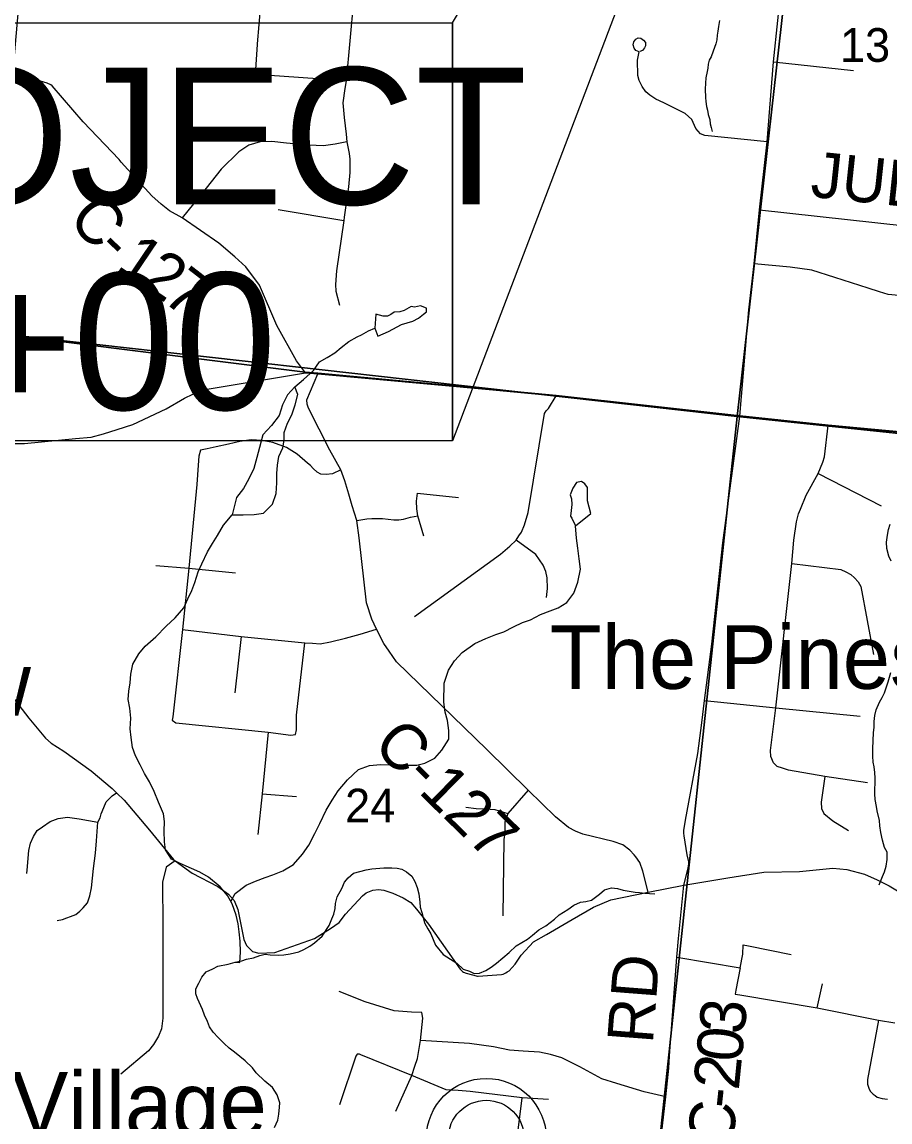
# Model space of a CAD drawing. Extents: x 0 to 43.4, y -8.1 to 22.
# Drawn here: x 5.839 to 6.917, y 16.475 to 17.842 of the extents above; entities that cross this region are included whole.
import ezdxf

# ---------------------------------------------------------------- set-up
doc = ezdxf.new("R2010")
doc.units = 0
for name, color, linetype in [('GM_X_Corporation', 7, 'Continuous'), ('GM_X_County_Road', 7, 'Continuous'), ('GM_X_County_Road_Text', 7, 'Continuous'), ('GM_X_Minor_Lake', 7, 'Continuous'), ('GM_X_Minor_River', 7, 'Continuous'), ('GM_X_Section_Text', 7, 'Continuous'), ('GM_X_Township_Road', 7, 'Continuous'), ('GM_X_Unincorporated', 7, 'Continuous'), ('GM_X_Unincorporated_Text', 7, 'Continuous'), ('SH_Masking', 7, 'Continuous'), ('SH_Text', 7, 'Continuous')]:
    doc.layers.add(name, color=color, linetype=linetype)

msp = doc.modelspace()

# ---------------------------------------------------------------- linework, layer by layer
at = {"layer": 'GM_X_Corporation'}
for points in [[(6.8431, 18.3799), (6.7271, 17.3517), (5.7989, 17.456), (5.8893, 18.4791)], [(6.8431, 18.3799), (7.8526, 18.2674), (7.7575, 17.2431), (6.7271, 17.3517)], [(6.7271, 17.3517), (6.6267, 16.4119), (5.7092, 16.4607), (5.7989, 17.456)], [(7.7575, 17.2431), (7.6501, 16.228), (6.6267, 16.4119), (6.7271, 17.3517)]]:
    msp.add_lwpolyline(points, close=True, dxfattribs=at)
for points in [[(6.9337, 17.3322), (6.8401, 17.341), (6.7303, 17.3528), (6.5022, 17.378), (6.4189, 17.3857), (6.2062, 17.4054), (6.1906, 17.4067), (5.7944, 17.4564), (5.4373, 17.5131), (4.8521, 17.6061), (4.4612, 17.6488), (4.3821, 17.6581), (4.1644, 17.6753)], [(4.1644, 17.6753), (4.3821, 17.6581), (4.4612, 17.6488), (4.8521, 17.6061), (5.4373, 17.5131), (5.7944, 17.4564), (6.1906, 17.4067), (6.2062, 17.4054), (6.4189, 17.3857), (6.5022, 17.378), (6.7303, 17.3528), (6.8401, 17.341), (6.9337, 17.3322)]]:
    msp.add_lwpolyline(points, dxfattribs=at)
at = {"layer": 'GM_X_County_Road'}
msp.add_line((6.1909, 17.4062), (6.2065, 17.4049), dxfattribs=at)
for points in [[(6.755, 17.6085), (6.7645, 17.6929), (6.7721, 17.7923), (6.7884, 17.9468), (6.7919, 17.9787), (6.8164, 18.1721), (6.8285, 18.2944), (6.8309, 18.3175)], [(5.9623, 17.6678), (5.9596, 17.6709), (5.915, 17.7177), (5.8763, 17.7626), (5.8748, 17.7638), (5.8703, 17.7658), (5.8485, 17.7726), (5.8243, 17.7859)], [(6.1909, 17.4062), (6.1798, 17.4209), (6.1554, 17.4646), (6.1338, 17.5151), (6.117, 17.5377), (6.1032, 17.55), (6.0836, 17.5671), (6.0379, 17.5987), (6.0222, 17.6072), (6.012, 17.6154), (6.0002, 17.626), (5.9623, 17.6678)], [(6.7305, 17.3523), (6.7417, 17.4843), (6.7481, 17.5416), (6.755, 17.6085)], [(6.755, 17.6085), (6.9735, 17.5845), (7.2654, 17.5541)], [(5.8217, 17.3184), (5.8422, 17.3182), (5.9056, 17.3244), (5.9247, 17.3259), (5.9403, 17.3303), (5.9573, 17.3355), (5.9766, 17.342), (6.018, 17.3613), (6.041, 17.3746), (6.0616, 17.3843), (6.1909, 17.4062)], [(6.6168, 16.7608), (6.61, 16.7869), (6.6061, 16.7976), (6.6012, 16.8049), (6.5991, 16.8073), (6.5939, 16.813), (6.585, 16.8199), (6.5733, 16.8237), (6.5355, 16.8329), (6.5262, 16.8367), (6.5175, 16.8412), (6.5015, 16.8545), (6.4676, 16.8877), (6.4161, 16.9382), (6.304, 17.0472), (6.2948, 17.0603), (6.2885, 17.07), (6.2791, 17.0875), (6.2733, 17.0999), (6.2669, 17.1205), (6.2578, 17.2011), (6.2547, 17.2226), (6.2489, 17.2407), (6.2448, 17.2553), (6.24, 17.272), (6.2351, 17.2857), (6.2214, 17.31), (6.1948, 17.3621), (6.193, 17.3671), (6.1928, 17.3724), (6.2065, 17.4049)], [(6.2065, 17.4049), (6.4191, 17.3852), (6.5024, 17.3775), (6.7305, 17.3523), (6.8403, 17.3405), (6.934, 17.3317), (7.0194, 17.3221), (7.1459, 17.3085), (7.2379, 17.2981), (7.3491, 17.2862), (7.3995, 17.281), (7.6127, 17.2515), (7.6512, 17.2473), (7.707, 17.2463), (7.7489, 17.2401), (7.8001, 17.2378), (7.885, 17.2341), (7.9438, 17.2315), (8.0044, 17.2296), (8.0566, 17.228), (8.1392, 17.2232), (8.1943, 17.2214)], [(6.6432, 16.5578), (6.652, 16.6803), (6.6544, 16.7036), (6.6608, 16.7698), (6.6662, 16.7909), (6.6671, 16.7961), (6.667, 16.7987), (6.6651, 16.8073), (6.6613, 16.8309), (6.6609, 16.8341), (6.6608, 16.8374), (6.663, 16.8502), (6.6784, 16.9333), (6.6831, 16.9711), (6.6866, 16.9991), (6.6955, 17.0691), (6.7092, 17.1947), (6.7305, 17.3523)], [(5.8185, 17.0146), (5.8473, 16.9772), (5.868, 16.9524), (5.8751, 16.9462), (5.8908, 16.936), (5.9251, 16.9118), (5.9508, 16.8896), (5.9565, 16.8842), (5.966, 16.8752), (5.9975, 16.8381), (6.027, 16.8014), (6.0292, 16.7998), (6.0382, 16.7932), (6.0505, 16.7846), (6.0824, 16.768), (6.0955, 16.7586), (6.1025, 16.7505), (6.1072, 16.7394), (6.1099, 16.7249), (6.1143, 16.7021), (6.1176, 16.6948), (6.1254, 16.6874), (6.1333, 16.685), (6.153, 16.6861), (6.2023, 16.7036), (6.2223, 16.716), (6.2327, 16.7234), (6.2406, 16.7338), (6.2619, 16.7565), (6.2665, 16.7602), (6.2746, 16.7634), (6.2816, 16.7641), (6.2882, 16.7635), (6.2995, 16.7599), (6.3123, 16.7539), (6.3217, 16.748), (6.3291, 16.7399), (6.3438, 16.7214), (6.3832, 16.6655), (6.386, 16.6624), (6.3873, 16.6615), (6.3906, 16.6604), (6.4045, 16.6568), (6.4054, 16.6567), (6.4346, 16.6587), (6.4366, 16.6592), (6.4397, 16.6608), (6.4415, 16.6618), (6.4441, 16.6634), (6.4516, 16.6716), (6.459, 16.6828), (6.4742, 16.6992), (6.4903, 16.7083), (6.5222, 16.727), (6.5487, 16.7423), (6.5594, 16.7468)], [(6.6168, 16.7608), (6.6608, 16.7698), (6.7156, 16.7789), (6.7602, 16.7859), (6.8046, 16.7868), (6.846, 16.7908), (6.8634, 16.7893), (6.8853, 16.7835), (6.901, 16.7764), (6.916, 16.7688), (6.9303, 16.7602)], [(6.5594, 16.7468), (6.5701, 16.7513), (6.6168, 16.7608)], [(6.6315, 16.4453), (6.6384, 16.5068), (6.6421, 16.5425), (6.6432, 16.5578)]]:
    msp.add_lwpolyline(points, dxfattribs=at)
at = {"layer": 'GM_X_Minor_Lake'}
for points in [[(6.2772, 17.4615), (6.2811, 17.4515), (6.2942, 17.4573), (6.3103, 17.4659), (6.3245, 17.4701), (6.3314, 17.4741), (6.3376, 17.4789), (6.3415, 17.4818), (6.3412, 17.4864), (6.3337, 17.4892), (6.3265, 17.4875), (6.3223, 17.4884), (6.3135, 17.4833), (6.3081, 17.4816), (6.3013, 17.4814), (6.297, 17.4784), (6.2928, 17.4763), (6.2875, 17.4764), (6.2784, 17.4789)], [(6.2784, 17.4789), (6.2772, 17.4615)], [(6.1, 17.2297), (6.1135, 17.2297), (6.1272, 17.2301), (6.139, 17.2317), (6.1499, 17.2428), (6.1548, 17.2563), (6.1555, 17.2692), (6.1555, 17.281), (6.1561, 17.2912), (6.1579, 17.3022), (6.1628, 17.3127), (6.1645, 17.3225), (6.1644, 17.332), (6.1689, 17.3436), (6.1741, 17.3537), (6.1782, 17.3662), (6.1816, 17.379), (6.1777, 17.3886), (6.1687, 17.3786), (6.1627, 17.3662), (6.1585, 17.353), (6.1487, 17.3408), (6.1381, 17.3289), (6.1339, 17.3134), (6.1306, 17.301), (6.1268, 17.287), (6.1207, 17.2743), (6.114, 17.2623), (6.1053, 17.2512)], [(6.5262, 17.216), (6.5455, 17.2311), (6.5414, 17.2472), (6.5414, 17.2635), (6.5378, 17.2681), (6.5337, 17.2709), (6.5276, 17.2699), (6.5232, 17.2628), (6.5199, 17.2546), (6.5213, 17.2496), (6.5219, 17.2424), (6.521, 17.2352), (6.52, 17.228), (6.5218, 17.2253)], [(6.1053, 17.2512), (6.1, 17.2297)], [(6.5218, 17.2253), (6.5262, 17.216)]]:
    msp.add_lwpolyline(points, dxfattribs=at)
at = {"layer": 'GM_X_Minor_River'}
for points in [[(6.7053, 17.8436), (6.7039, 17.836), (6.7033, 17.8303), (6.7023, 17.8254), (6.7018, 17.8197), (6.7008, 17.8148), (6.6975, 17.8054), (6.695, 17.7987), (6.6925, 17.7942), (6.6912, 17.7893), (6.6907, 17.7844), (6.6898, 17.7803), (6.6884, 17.7723), (6.6878, 17.7659), (6.6875, 17.7583), (6.6879, 17.748), (6.6881, 17.7431), (6.689, 17.7369), (6.6904, 17.7323), (6.691, 17.727), (6.693, 17.7205), (6.6936, 17.7151), (6.695, 17.7109), (6.6959, 17.7059)], [(6.1777, 17.3886), (6.1886, 17.3978), (6.201, 17.4089), (6.2085, 17.4197), (6.2178, 17.4251), (6.2274, 17.4309), (6.2352, 17.4376), (6.2449, 17.4449), (6.2553, 17.4507), (6.2606, 17.4532), (6.2691, 17.4583), (6.2772, 17.4615)], [(6.1043, 16.6739), (6.1094, 16.6735), (6.1105, 16.6863), (6.11, 16.7), (6.1088, 16.7118), (6.1076, 16.7217), (6.1048, 16.7324), (6.1002, 16.7466), (6.094, 16.757), (6.0852, 16.7675), (6.0707, 16.7796), (6.0599, 16.7856), (6.0493, 16.7904), (6.0355, 16.7965), (6.0246, 16.8021), (6.0173, 16.8136), (6.016, 16.8235), (6.0156, 16.8368), (6.0159, 16.8486), (6.0146, 16.8581), (6.0085, 16.8727), (6.0032, 16.8858), (5.9974, 16.8981), (5.9912, 16.9085), (5.9858, 16.9192), (5.98, 16.9304), (5.9761, 16.9408), (5.9745, 16.9529), (5.9733, 16.964), (5.974, 16.9769), (5.9728, 16.9894), (5.9708, 17.0001), (5.9718, 17.0107), (5.9732, 17.021), (5.9743, 17.0316), (5.9768, 17.044), (5.984, 17.0568), (5.9918, 17.0664), (6.0054, 17.0779), (6.0179, 17.0912), (6.0292, 17.1016), (6.0401, 17.1142), (6.0449, 17.1251), (6.0501, 17.1356), (6.0538, 17.1454), (6.0576, 17.159), (6.0624, 17.1687), (6.0692, 17.1838), (6.0755, 17.1942), (6.0819, 17.204), (6.0894, 17.2167), (6.1, 17.2297)], [(6.0985, 16.7495), (6.1036, 16.7594), (6.1175, 16.7697), (6.129, 16.7748), (6.1409, 16.779), (6.1505, 16.7826), (6.1628, 16.7876), (6.1762, 16.7952), (6.1872, 16.8082), (6.1951, 16.8194), (6.2026, 16.8337), (6.2087, 16.8464), (6.2167, 16.8626), (6.2242, 16.8753), (6.2317, 16.8869), (6.2431, 16.9006), (6.257, 16.9132), (6.2704, 16.9182), (6.2841, 16.9194), (6.297, 16.919), (6.3084, 16.9195), (6.3183, 16.9189), (6.3293, 16.9186), (6.3392, 16.921), (6.3515, 16.9272), (6.3605, 16.9372), (6.3692, 16.951), (6.3691, 16.9617), (6.3675, 16.9742), (6.3647, 16.9846), (6.3628, 16.9968), (6.3634, 17.0207), (6.3687, 17.0369), (6.3762, 17.0481), (6.3856, 17.0585), (6.4014, 17.0699), (6.4149, 17.076), (6.4275, 17.081), (6.4375, 17.0845), (6.4494, 17.0907), (6.4606, 17.0957), (6.4705, 17.0993), (6.4828, 17.1058), (6.4951, 17.1104), (6.5047, 17.114), (6.5155, 17.1209), (6.5245, 17.1325), (6.5294, 17.146), (6.5325, 17.1623), (6.5309, 17.1749), (6.5293, 17.1882), (6.5277, 17.2008), (6.5262, 17.216)], [(6.9183, 17.172), (6.9153, 17.1782), (6.9128, 17.1877), (6.9126, 17.1957), (6.9139, 17.2044), (6.9152, 17.2116), (6.9172, 17.218)], [(6.9033, 16.7701), (6.9077, 16.7803), (6.9101, 16.7863), (6.9121, 16.7931), (6.9134, 16.8015), (6.9132, 16.8106), (6.9099, 16.8164), (6.9077, 16.8255), (6.9056, 16.8351), (6.9043, 16.8435), (6.904, 16.8499), (6.9011, 16.8618), (6.9001, 16.8675), (6.8987, 16.8759), (6.8981, 16.8831), (6.8982, 16.8892), (6.8987, 16.896), (6.8985, 16.9025), (6.8982, 16.9097), (6.8972, 16.9166), (6.8961, 16.9223), (6.8955, 16.9299), (6.8957, 16.939), (6.8964, 16.9592), (6.8973, 16.9656), (6.8974, 16.9728), (6.898, 16.9804), (6.8996, 16.9876), (6.904, 16.997), (6.9072, 17.0027), (6.9099, 17.0087), (6.9123, 17.0148), (6.9148, 17.0223), (6.918, 17.034)], [(6.1524, 16.4688), (6.1567, 16.4778), (6.158, 16.4854), (6.1589, 16.4938), (6.1594, 16.4994), (6.1558, 16.5094), (6.1502, 16.5182), (6.1404, 16.5264), (6.1296, 16.5365), (6.1251, 16.5426), (6.1161, 16.5515), (6.1029, 16.5624), (6.0961, 16.5671), (6.0901, 16.5729), (6.0826, 16.5803), (6.0763, 16.5872), (6.0718, 16.5938), (6.0692, 16.6003), (6.0656, 16.6083), (6.063, 16.6152), (6.0568, 16.629), (6.055, 16.6347), (6.0547, 16.6408), (6.0587, 16.648), (6.0622, 16.6555), (6.0677, 16.6619), (6.0758, 16.6659), (6.0823, 16.6692), (6.095, 16.6717), (6.1038, 16.6738), (6.1119, 16.6755), (6.118, 16.6777), (6.1264, 16.6795), (6.1345, 16.6824), (6.141, 16.6838), (6.1471, 16.6833), (6.1574, 16.6827), (6.1643, 16.6833), (6.172, 16.6843), (6.1827, 16.6868), (6.1889, 16.6897), (6.1966, 16.6938), (6.2024, 16.6982), (6.2117, 16.7061), (6.2203, 16.7196), (6.2239, 16.7279), (6.2263, 16.7336), (6.228, 16.7407), (6.2285, 16.7468), (6.2305, 16.7551), (6.2361, 16.7653), (6.2397, 16.7732), (6.244, 16.7789), (6.2506, 16.7844), (6.2663, 16.7887), (6.2736, 16.7901), (6.2885, 16.791), (6.2984, 16.7912), (6.3049, 16.7907), (6.3106, 16.7894), (6.3166, 16.7863), (6.323, 16.7809), (6.3267, 16.774), (6.3297, 16.7667), (6.3318, 16.7587), (6.3331, 16.7484)], [(6.3331, 16.7484), (6.3334, 16.7423), (6.3356, 16.7358), (6.3388, 16.7228), (6.3429, 16.7155), (6.3466, 16.709), (6.3524, 16.6952), (6.3621, 16.6836), (6.3712, 16.6777), (6.3791, 16.6727), (6.387, 16.6653), (6.3946, 16.6629), (6.4007, 16.6601), (6.4071, 16.6604), (6.4152, 16.6637), (6.4218, 16.6677), (6.4284, 16.6729), (6.4439, 16.6859), (6.4528, 16.6942), (6.4598, 16.6986), (6.4667, 16.7026), (6.4729, 16.7075), (6.4807, 16.7142), (6.4896, 16.7193), (6.5004, 16.7275), (6.5062, 16.7327), (6.5167, 16.7394), (6.5244, 16.7449), (6.5325, 16.7486), (6.539, 16.7493), (6.5463, 16.751), (6.556, 16.7585), (6.5622, 16.764), (6.571, 16.7662), (6.5786, 16.7653), (6.5855, 16.7636), (6.5931, 16.7624), (6.6003, 16.7611), (6.606, 16.7606), (6.6125, 16.7597), (6.6182, 16.7592), (6.6247, 16.7587)]]:
    msp.add_lwpolyline(points, dxfattribs=at)
at = {"layer": 'GM_X_Township_Road'}
for p, q in [((6.7721, 17.7923), (6.8717, 17.7815)), ((6.157, 17.6088), (6.2385, 17.5951)), ((6.8276, 17.2811), (6.9059, 17.241)), ((6.111, 17.0784), (6.1032, 17.0084)), ((6.1371, 16.8831), (6.1798, 16.8796)), ((6.8266, 16.6171), (6.833, 16.647))]:
    msp.add_line(p, q, dxfattribs=at)
for points in [[(6.1315, 17.8148), (6.1357, 17.8625), (6.1385, 17.8756), (6.143, 17.8836), (6.1526, 17.8901), (6.1668, 17.8977), (6.1775, 17.9067), (6.1847, 17.9188), (6.1906, 17.9354), (6.1902, 17.9493), (6.1999, 18.0128)], [(6.2537, 17.8775), (6.2505, 17.868), (6.2415, 17.7685), (6.2401, 17.7591)], [(6.7645, 17.6929), (6.6868, 17.7008), (6.6816, 17.7027), (6.676, 17.7097), (6.671, 17.7208), (6.6627, 17.7282), (6.636, 17.7415), (6.626, 17.746), (6.6187, 17.7508), (6.6139, 17.7551), (6.609, 17.7617), (6.6053, 17.7692), (6.6038, 17.7752), (6.6034, 17.7945), (6.6053, 17.8047), (6.6014, 17.8062), (6.5993, 17.8092), (6.5981, 17.8133), (6.5986, 17.817), (6.6011, 17.8205), (6.604, 17.822), (6.6077, 17.8215), (6.611, 17.8193), (6.6131, 17.8162), (6.6132, 17.8123), (6.6121, 17.8096), (6.6094, 17.8063), (6.6063, 17.8051)], [(6.129, 17.7764), (6.1314, 17.8139), (6.1315, 17.8148)], [(6.2415, 17.7685), (6.129, 17.7764), (6.071, 17.7807)], [(6.2401, 17.7591), (6.2375, 17.7413), (6.239, 17.7233), (6.2415, 17.7025)], [(6.2415, 17.7025), (6.2426, 17.693), (6.2451, 17.6785), (6.2462, 17.6713), (6.2461, 17.6626), (6.246, 17.655), (6.2445, 17.6372), (6.2399, 17.6052)], [(6.2426, 17.693), (6.2281, 17.6901), (6.2136, 17.688), (6.1954, 17.689), (6.1675, 17.6912), (6.1493, 17.6934), (6.1348, 17.693), (6.1207, 17.689), (6.1083, 17.6807), (6.0862, 17.6589), (6.0677, 17.6353), (6.0379, 17.5987)], [(6.2399, 17.6052), (6.2391, 17.5994), (6.2385, 17.5951), (6.2297, 17.5328), (6.2282, 17.5158), (6.2287, 17.5074), (6.2333, 17.4899)], [(6.9631, 17.4989), (6.9145, 17.5033), (6.9038, 17.5066), (6.8897, 17.5111), (6.8484, 17.5245), (6.82, 17.5337), (6.7928, 17.5374), (6.7481, 17.5416)], [(6.3264, 17.1034), (6.4333, 17.1809), (6.4448, 17.1908), (6.4525, 17.1982), (6.4558, 17.2034), (6.4593, 17.2083), (6.463, 17.2174), (6.4677, 17.2327), (6.4878, 17.3554), (6.4898, 17.3588), (6.4929, 17.3617), (6.5024, 17.3775)], [(6.8889, 16.8969), (6.8362, 16.9046), (6.791, 16.9126), (6.7833, 16.915), (6.777, 16.9172), (6.7724, 16.9215), (6.769, 16.9295), (6.7686, 16.9369), (6.7751, 16.9901), (6.7949, 17.1693), (6.7973, 17.1982), (6.801, 17.2211), (6.8033, 17.2307), (6.8057, 17.2367), (6.8127, 17.2542), (6.8276, 17.2811), (6.8337, 17.2949), (6.8354, 17.3017), (6.8403, 17.3405)], [(6.2351, 17.2857), (6.2248, 17.2807), (6.2167, 17.2797), (6.2103, 17.2803), (6.2056, 17.2828), (6.2007, 17.2873), (6.1974, 17.2908), (6.1936, 17.2939), (6.1807, 17.305), (6.1675, 17.3131), (6.1503, 17.3195), (6.1367, 17.3221), (6.1235, 17.3226), (6.1095, 17.3209), (6.0953, 17.3174), (6.0802, 17.3143), (6.0691, 17.3118), (6.0606, 17.3098), (6.0588, 17.3026), (6.0579, 17.2915), (6.0561, 17.2675), (6.046, 17.1632), (6.0384, 17.0873), (6.0262, 16.9788), (6.0256, 16.9746), (6.0301, 16.9714), (6.1446, 16.9596), (6.173, 16.9561), (6.1786, 16.9569), (6.1798, 16.9627), (6.18, 16.9809), (6.1901, 17.0706)], [(6.338, 17.203), (6.3306, 17.2283), (6.3295, 17.237), (6.3291, 17.2465), (6.3302, 17.2566), (6.3811, 17.2512)], [(6.2547, 17.2226), (6.2671, 17.2248), (6.2735, 17.2252), (6.2867, 17.225), (6.3009, 17.2234), (6.3071, 17.2236), (6.3128, 17.2244), (6.3213, 17.2267), (6.3306, 17.2283)], [(6.4904, 17.1269), (6.4914, 17.138), (6.491, 17.1512), (6.4896, 17.1594), (6.4861, 17.1673), (6.4772, 17.1805), (6.4525, 17.1982)], [(6.0052, 17.1669), (6.046, 17.1632), (6.1041, 17.1574)], [(6.7949, 17.1693), (6.856, 17.1619), (6.8621, 17.159), (6.8684, 17.1554), (6.8728, 17.1515), (6.8774, 17.1464), (6.8806, 17.1407), (6.8966, 17.0561)], [(6.0384, 17.0873), (6.111, 17.0784), (6.1901, 17.0706), (6.1997, 17.0702), (6.2094, 17.0696), (6.2221, 17.0717), (6.2408, 17.0765), (6.259, 17.0813), (6.2791, 17.0875)], [(6.6866, 16.9991), (6.7751, 16.9901), (6.8797, 16.9794)], [(6.1446, 16.9596), (6.1371, 16.8831), (6.1318, 16.8326)], [(6.8362, 16.9046), (6.8315, 16.8726), (6.8318, 16.8649), (6.8349, 16.8586), (6.8458, 16.8496), (6.8652, 16.8374)], [(6.4676, 16.8877), (6.4425, 16.8588), (6.4387, 16.848), (6.4388, 16.8346), (6.4375, 16.8263), (6.4362, 16.7315)], [(5.8828, 16.7257), (5.8891, 16.7268), (5.8945, 16.7289), (5.8992, 16.7307), (5.9057, 16.7334), (5.9109, 16.7373), (5.9151, 16.7416), (5.9204, 16.7478), (5.9233, 16.7562), (5.9254, 16.7662), (5.928, 16.7905), (5.9303, 16.8093), (5.9317, 16.8248), (5.9332, 16.8479), (5.9359, 16.8532), (5.9375, 16.8583), (5.9406, 16.8663), (5.9437, 16.8732), (5.9483, 16.8781), (5.951, 16.8808), (5.9565, 16.8842)], [(6.3901, 16.8665), (6.4032, 16.865), (6.414, 16.8646), (6.4263, 16.8638), (6.4425, 16.8588)], [(5.8451, 16.7843), (5.8458, 16.793), (5.8466, 16.8033), (5.8474, 16.8128), (5.8495, 16.8217), (5.8534, 16.8301), (5.8578, 16.8375), (5.8643, 16.842), (5.8738, 16.8487), (5.8841, 16.8526), (5.8955, 16.8542), (5.9099, 16.852), (5.9332, 16.8479)], [(6.0292, 16.7998), (6.0181, 16.7921), (6.0135, 16.7735), (6.0135, 16.7587), (6.0137, 16.7341), (6.0141, 16.6421), (6.0139, 16.6046), (6.0121, 16.591), (6.0084, 16.5819), (6.0024, 16.5718), (5.9961, 16.564), (5.9616, 16.5347)], [(6.731, 16.667), (6.734, 16.684), (6.7347, 16.6955), (6.7413, 16.6941), (6.794, 16.6837)], [(6.652, 16.6803), (6.731, 16.667), (6.7253, 16.6392), (6.7248, 16.6343), (6.7305, 16.6334), (6.8266, 16.6171), (6.9028, 16.6021), (6.9229, 16.5988)], [(6.3032, 16.489), (6.3231, 16.5334), (6.3267, 16.5448), (6.3302, 16.5544), (6.3338, 16.5768), (6.3367, 16.6043), (6.3356, 16.6114), (6.3228, 16.6121), (6.3011, 16.6135), (6.2651, 16.6249), (6.2327, 16.6377)], [(6.9028, 16.6021), (6.8888, 16.5282), (6.8889, 16.5225), (6.8905, 16.5174), (6.8924, 16.5139), (6.8961, 16.51), (6.8984, 16.5083), (6.901, 16.5065), (6.9071, 16.5047), (6.9137, 16.504)], [(6.6384, 16.5068), (6.6117, 16.5128), (6.5779, 16.5235), (6.5591, 16.5293), (6.5318, 16.5438), (6.5092, 16.5553), (6.4955, 16.5592), (6.4815, 16.5623), (6.4612, 16.5633), (6.4443, 16.5646), (6.4244, 16.569), (6.3948, 16.5728), (6.3338, 16.5768)], [(6.493, 16.5034), (6.46, 16.5055), (6.3957, 16.5132), (6.3806, 16.5146), (6.3658, 16.5153), (6.3231, 16.5334), (6.2598, 16.559), (6.2583, 16.5596), (6.2568, 16.5599), (6.2554, 16.5596), (6.2542, 16.5585), (6.2534, 16.5572), (6.2334, 16.4966)], [(6.4252, 16.2466), (6.432, 16.2688), (6.4339, 16.2749), (6.435, 16.2811), (6.4417, 16.3375), (6.453, 16.4489), (6.46, 16.5055)]]:
    msp.add_lwpolyline(points, dxfattribs=at)
at = {"layer": 'GM_X_Unincorporated'}
for radius in [0.0744, 0.0472]:
    msp.add_circle((6.4156, 16.4552), radius, dxfattribs=at)
at = {"layer": 'SH_Masking'}
msp.add_lwpolyline([(4.6164, 17.8409), (6.3738, 17.8409), (6.3738, 17.3215), (4.6164, 17.3215)], close=True, dxfattribs=at)
at = {"layer": 'SH_Text'}
for points in [[(6.3738, 17.8409), (6.9134, 18.7404), (6.3738, 17.3215)], [(4.6164, 17.8409), (6.3738, 17.8409), (6.3738, 17.3215), (4.6164, 17.3215)]]:
    msp.add_lwpolyline(points, close=True, dxfattribs=at)

# ---------------------------------------------------------------- texts
at = {"layer": 'GM_X_County_Road_Text'}
for s, height, rotation, p in [('JULMAR RD', 0.05682, 353.9278, (6.817, 17.6249)), ('C', 0.0568, 311.7299, (5.8946, 17.5964)), ('-', 0.0568, 316.0318, (5.9289, 17.5582)), ('1', 0.0568, 325.9496, (5.954, 17.5353)), ('2', 0.0568, 326.1697, (5.9832, 17.5155)), ('7', 0.0568, 322.2204, (6.0114, 17.4967)), ('C-127', 0.05682, 315.5865, (6.2728, 16.9413)), ('RD', 0.05682, 85.5636, (6.6223, 16.5719)), ('3', 0.0568, 84.3504, (6.7359, 16.5832)), ('0', 0.0568, 84.3347, (6.7324, 16.5486)), ('2', 0.0568, 84.2643, (6.729, 16.514)), ('-', 0.0568, 83.9301, (6.7265, 16.4907)), ('C', 0.0568, 83.5847, (6.7213, 16.4443))]:
    msp.add_text(s, height=height, rotation=rotation, dxfattribs=at).set_placement(p)
at = {"layer": 'GM_X_Section_Text'}
for s, p in [('13', (6.8548, 17.7923)), ('24', (6.2402, 16.8476))]:
    msp.add_text(s, height=0.04186, rotation=0, dxfattribs=at).set_placement(p)
at = {"layer": 'GM_X_Unincorporated_Text'}
for s, height, p in [('The Pines', 0.07898, (6.4943, 17.0135)), ('Mountview', 0.07898, (5.3452, 16.9801)), ('Cotillion Village', 0.078977, (5.421, 16.4585))]:
    msp.add_text(s, height=height, rotation=0, dxfattribs=at).set_placement(p)
at = {"layer": 'SH_Text'}
for s, p in [('BEGIN PROJECT', (4.6347, 17.6152)), ('STA. 114+00', (4.8216, 17.3602))]:
    msp.add_text(s, height=0.17, dxfattribs=at).set_placement(p)

doc.saveas('drawing.dxf')
